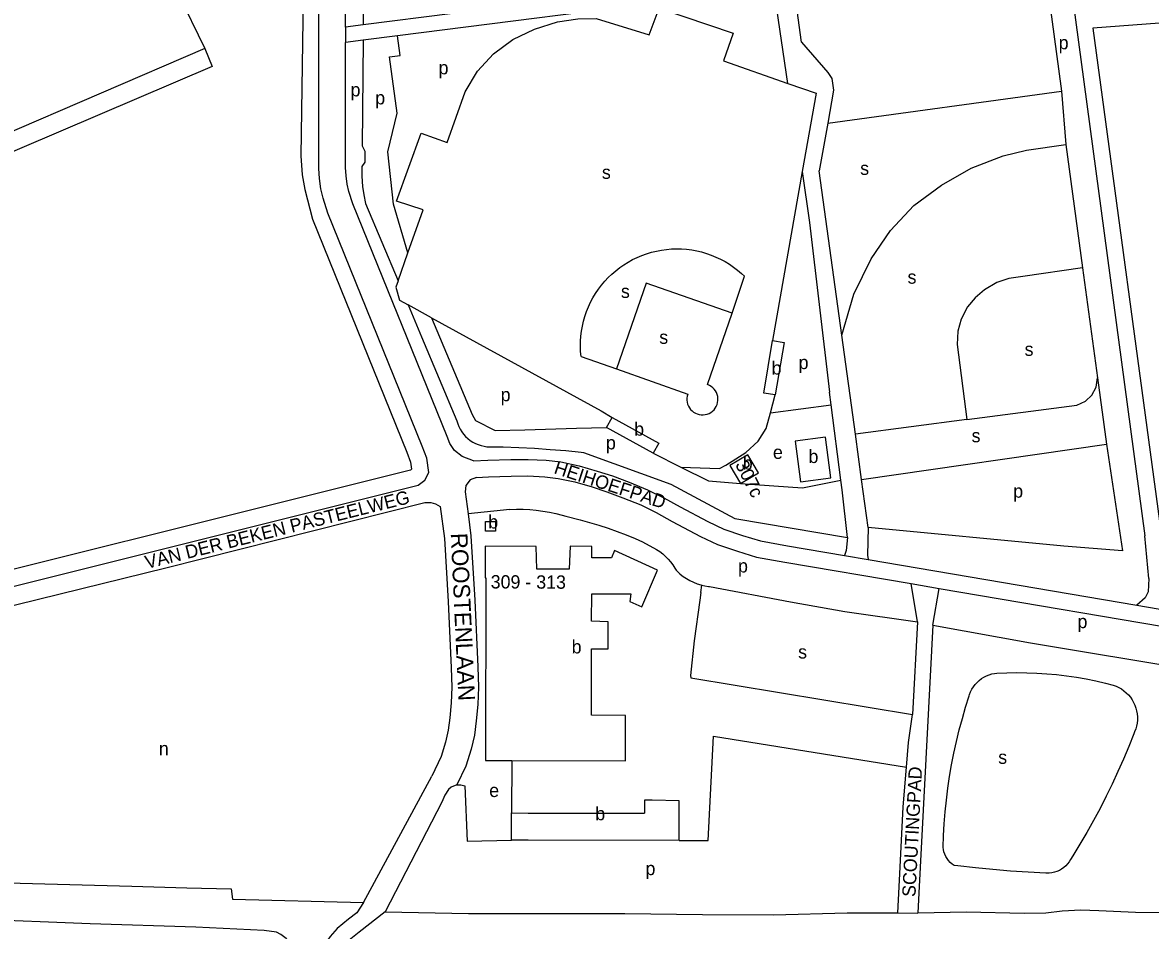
# Model space of a CAD drawing. Extents: x 161093 to 163177, y 379000 to 380904.
# Drawn here: x 162069 to 162407.9, y 379600.5 to 379873.5 of the extents above; entities that cross this region are included whole.
import ezdxf

# ---------------------------------------------------------------- set-up
doc = ezdxf.new("R2010")
doc.units = 0
for name, color, linetype in [('BLT_Basislijn', 7, 'Continuous'), ('BLT_Bebouwing', 7, 'Continuous'), ('BLT_Centroide', 7, 'Continuous'), ('BLT_Huisnummer', 7, 'Continuous'), ('BLT_Huisnummer_reeks', 7, 'Continuous'), ('BLT_Straatnaam', 7, 'Continuous'), ('BLT_Straatnaam_verkleind', 7, 'Continuous')]:
    doc.layers.add(name, color=color, linetype=linetype)

msp = doc.modelspace()

# ---------------------------------------------------------------- linework, layer by layer
at = {"layer": 'BLT_Basislijn'}
for p, q in [((162378.62, 379925.25), (162406.17, 379719.19)), ((162153.42, 379885.29), (162152.67, 379833.48)), ((162294.71, 379884.06), (162181.67, 379869.53)), ((162298.98, 379855.19), (162294.71, 379884.06)), ((162171.37, 379872.79), (162166.01, 379872.11)), ((162166.01, 379872.11), (162166.02, 379867.52)), ((162181.67, 379869.53), (162171.33, 379868.2)), ((162390.62, 379871.78), (162411.12, 379719.86)), ((162171.33, 379868.2), (162166.02, 379867.52)), ((162123.8, 379865.74), (162013.53, 379818.24)), ((162310.93, 379843.25), (162381.18, 379852.9)), ((162381.18, 379852.9), (162382.49, 379836.84)), ((162382.49, 379836.84), (162387.49, 379799.81)), ((162303.23, 379828.69), (162294.38, 379777.9)), ((162303.23, 379828.69), (162305.5, 379813.39)), ((162172.07, 379819.1), (162181.83, 379795.89)), ((162305.5, 379813.39), (162311.45, 379762.39)), ((162181.83, 379795.89), (162184.82, 379804.31)), ((162387.49, 379799.81), (162391.98, 379766.71)), ((162282.18, 379786.18), (162285.96, 379797.21)), ((162184.88, 379788.63), (162188.93, 379779)), ((162191.93, 379784.76), (162184.88, 379788.63)), ((162191.93, 379784.76), (162204.15, 379755.69)), ((162274.81, 379764.64), (162282.18, 379786.18)), ((162188.93, 379779), (162199.54, 379753.75)), ((162236.83, 379773.13), (162247.44, 379769.38)), ((162247.44, 379769.38), (162268.89, 379761.78)), ((162391.98, 379766.71), (162394.72, 379746.73)), ((162293.72, 379756.17), (162295.19, 379761.55)), ((162311.94, 379758.61), (162311.45, 379762.39)), ((162293.72, 379756.17), (162311.94, 379758.61)), ((162314.88, 379735.89), (162311.94, 379758.61)), ((162242.88, 379756.79), (162246.14, 379754.78)), ((162352.74, 379754.15), (162319.26, 379749.71)), ((162321.13, 379736.15), (162319.26, 379749.71)), ((162321.13, 379736.15), (162394.72, 379746.73)), ((162315.26, 379732.98), (162314.88, 379735.89)), ((162323.12, 379721.67), (162321.13, 379736.15)), ((162316.89, 379718.68), (162315.26, 379732.98)), ((162215.44, 379727.12), (162202.86, 379725.75)), ((162232.22, 379725.08), (162236.57, 379723.99)), ((162255.3, 379717.36), (162259.51, 379715.05)), ((162407.37, 379706.38), (162406.17, 379719.19)), ((162272.77, 379702.15), (162273.07, 379704.38)), ((162337.89, 379693.3), (162335.99, 379704.81)), ((162342.48, 379692.3), (162344.38, 379703.38)), ((162337.89, 379693.3), (162336.41, 379665.42)), ((162342.48, 379692.3), (162338.34, 379611.84)), ((162269.82, 379676.5), (162336.41, 379665.42)), ((162335.24, 379657.03), (162336.41, 379665.42)), ((162216.05, 379651.66), (162215.91, 379635.86)), ((162332.04, 379605.84), (162332.72, 379619.57)), ((162338.34, 379611.84), (162338.01, 379605.69)), ((162332.04, 379605.84), (162338.01, 379605.69))]:
    msp.add_line(p, q, dxfattribs=at)
for points in [[(162160.75, 379816.24), (162159.29, 379820.67), (162158.68, 379823.55), (162158.25, 379826.59), (162158.02, 379829.61), (162158.01, 379873.49), (162158.25, 379931.81), (162158.67, 380027.65), (162158.78, 380047.6)], [(162166.01, 379872.11), (162166.25, 379931.78), (162166.67, 380027.84)], [(162171.8, 380008.48), (162171.73, 380000), (162171.83, 379985.21), (162171.58, 379944.32), (162171.46, 379881.89), (162171.37, 379872.79)], [(162067.03, 379977.72), (162075.14, 379965.67), (162123.8, 379865.74)], [(162367.14, 379959.73), (162371.63, 379923.75), (162381.18, 379852.9)], [(162303.04, 379867.59), (162291.99, 379948.53)], [(162196.38, 379891.02), (162198.3, 379876.22), (162171.37, 379872.79)], [(162567.03, 379892.57), (162455.56, 379878.15), (162418.63, 379873.91), (162390.62, 379871.78)], [(162184.82, 379804.31), (162189.38, 379817.17), (162181.39, 379819.82), (162188.75, 379840.23), (162196.57, 379837.41), (162201.99, 379852.7), (162205.66, 379858.87), (162210.55, 379864.14), (162216.34, 379868.38), (162222.85, 379871.49), (162229.7, 379873.76), (162235.88, 379874.67), (162241.35, 379874.72), (162257.33, 379869.81), (162260.33, 379877.83), (162282.55, 379870.3), (162279.66, 379862.02), (162298.98, 379855.19)], [(162184.82, 379804.31), (162180.48, 379818.86), (162178.79, 379834.64), (162181.58, 379846.28), (162179.29, 379863.24), (162182.43, 379863.65), (162181.67, 379869.53)], [(162204.46, 379741.71), (162201.06, 379743.07), (162198.83, 379744.89), (162197.39, 379746.92), (162196.56, 379749.1), (162168.27, 379818.99), (162167.03, 379822.75), (162166.56, 379824.95), (162166.21, 379827.46), (162166.02, 379829.91), (162166.02, 379867.52)], [(162171.33, 379868.2), (162171.01, 379836.47), (162171.86, 379834.86), (162171.81, 379831.57), (162170.96, 379830.25), (162170.92, 379827.37), (162171.13, 379824.27), (162171.56, 379821.74), (162172.07, 379819.1)], [(162303.04, 379867.59), (162310.92, 379858.52), (162312.13, 379856.66), (162312.71, 379853.18), (162310.93, 379843.25)], [(162123.8, 379865.74), (162125.94, 379860.32), (161988.77, 379801.65)], [(162298.98, 379855.19), (162307.47, 379852.31), (162303.23, 379828.69)], [(162310.93, 379843.25), (162308.36, 379828.96)], [(162315.16, 379779.53), (162318.73, 379791.8), (162323.95, 379802.51), (162329.82, 379810.96), (162336.8, 379818.52), (162345.1, 379824.61), (162354, 379829.77), (162363.63, 379833.41), (162370.63, 379835.13), (162382.49, 379836.84)], [(162152.67, 379833.48), (162153.02, 379827.68), (162153.86, 379823.29), (162156.11, 379814.36)], [(162315.16, 379779.53), (162308.36, 379828.96)], [(162190.48, 379742.58), (162189.12, 379746.18), (162160.75, 379816.24)], [(162156.11, 379814.36), (162184.46, 379744.36), (162185.61, 379741.33)], [(162236.83, 379773.13), (162236.69, 379774.65), (162236.64, 379776.17), (162236.66, 379777.7), (162236.77, 379779.22), (162236.95, 379780.73), (162237.22, 379782.23), (162237.56, 379783.72), (162237.98, 379785.18), (162238.48, 379786.62), (162239.05, 379788.03), (162239.69, 379789.41), (162240.41, 379790.76), (162241.19, 379792.07), (162242.05, 379793.33), (162242.96, 379794.54), (162243.95, 379795.71), (162244.99, 379796.82), (162246.08, 379797.88), (162247.24, 379798.88), (162248.44, 379799.82), (162249.69, 379800.69), (162250.98, 379801.49), (162252.32, 379802.23), (162253.69, 379802.89), (162255.09, 379803.49), (162256.52, 379804), (162257.98, 379804.45), (162259.46, 379804.81), (162260.96, 379805.1), (162262.47, 379805.3), (162263.99, 379805.43), (162265.51, 379805.48), (162267.03, 379805.45), (162268.55, 379805.34), (162270.07, 379805.15), (162271.57, 379804.88), (162273.05, 379804.53), (162274.51, 379804.1), (162275.95, 379803.6), (162277.36, 379803.02), (162278.74, 379802.37), (162280.08, 379801.65), (162281.38, 379800.86), (162282.64, 379800), (162283.86, 379799.08), (162285.02, 379798.09), (162285.96, 379797.21)], [(162387.49, 379799.81), (162369.55, 379797.12), (162365.35, 379796.55), (162361.78, 379795.34), (162357.99, 379793.16), (162355.24, 379790.79), (162352.93, 379788), (162351.02, 379784.32), (162350.04, 379780.69), (162349.83, 379776.7), (162352.74, 379754.15)], [(162181.83, 379795.89), (162181.14, 379793.96), (162182.32, 379790.03), (162184.88, 379788.63)], [(162282.18, 379786.18), (162256.36, 379795.12), (162247.44, 379769.38)], [(162191.93, 379784.76), (162242.88, 379756.79)], [(162319.26, 379749.71), (162315.16, 379779.53)], [(162268.89, 379761.78), (162268.73, 379761.2), (162268.64, 379760.59), (162268.63, 379759.98), (162268.7, 379759.37), (162268.85, 379758.78), (162269.08, 379758.21), (162269.38, 379757.68), (162269.74, 379757.19), (162270.17, 379756.76), (162270.65, 379756.38), (162271.18, 379756.07), (162271.74, 379755.82), (162272.33, 379755.66), (162272.93, 379755.57), (162273.54, 379755.56), (162274.15, 379755.64), (162274.74, 379755.79), (162275.31, 379756.01), (162275.84, 379756.31), (162276.33, 379756.68), (162276.77, 379757.1), (162277.14, 379757.58), (162277.46, 379758.11), (162277.7, 379758.67), (162277.86, 379759.26), (162277.95, 379759.86), (162277.96, 379760.47), (162277.88, 379761.08), (162277.73, 379761.67), (162277.51, 379762.24), (162277.21, 379762.77), (162276.84, 379763.26), (162276.42, 379763.7), (162275.93, 379764.08), (162275.41, 379764.39), (162274.81, 379764.64)], [(162352.74, 379754.15), (162385.77, 379758.52), (162388.34, 379759.64), (162390.33, 379761.51), (162391.59, 379763.91), (162391.98, 379766.71)], [(162204.15, 379755.69), (162205.08, 379753.9), (162210.99, 379750.87), (162219.91, 379751.02), (162235.42, 379751.57), (162244.46, 379751.72)], [(162266.85, 379739.82), (162278.43, 379739.43), (162280.3, 379740.47), (162286.3, 379744.28), (162290.01, 379747.6), (162292.42, 379751.42), (162293.72, 379756.17)], [(162199.54, 379753.75), (162199.8, 379752.89), (162200.13, 379752.04), (162200.53, 379751.23), (162201.01, 379750.46), (162201.55, 379749.73), (162202.15, 379749.05), (162202.81, 379748.43), (162203.52, 379747.87), (162204.28, 379747.38), (162205.08, 379746.95), (162205.92, 379746.6), (162206.78, 379746.32), (162207.67, 379746.12), (162208.56, 379745.99), (162208.75, 379745.98)], [(162208.75, 379745.98), (162213.45, 379745.9), (162218.15, 379745.74), (162222.85, 379745.51), (162227.54, 379745.19), (162232.22, 379744.8), (162236.9, 379744.32), (162237.55, 379744.25)], [(162237.55, 379744.25), (162263.75, 379734.74), (162283.04, 379724.37), (162316.89, 379718.68)], [(162394.72, 379746.73), (162399.46, 379714.71), (162381.91, 379716.11), (162323.12, 379721.67)], [(162185.61, 379741.33), (162185.91, 379739.2), (162185.61, 379738.96), (162014.73, 379696.21)], [(162015.88, 379691.47), (162187.88, 379734.37), (162189.84, 379735.93), (162191.1, 379738.2), (162190.48, 379742.58)], [(162204.46, 379741.71), (162208.85, 379741.95), (162215.72, 379742.11), (162220.91, 379742.18), (162226.35, 379741.91), (162230.75, 379741.4), (162236.21, 379740.28), (162241.67, 379738.67), (162246.26, 379737.18), (162251.23, 379735.29), (162256.83, 379733.06), (162261.67, 379730.63), (162266.63, 379727.88), (162274.9, 379723.48), (162279.71, 379721.22), (162285.32, 379719.32), (162290.69, 379717.68), (162298.88, 379716.2), (162315.93, 379713.3)], [(162258.47, 379744.01), (162266.85, 379739.82)], [(162266.85, 379739.82), (162275.07, 379735.71), (162284.75, 379734.93)], [(162205.36, 379736.75), (162203.5, 379735.99), (162202.22, 379734.32), (162201.97, 379732.4), (162202.86, 379725.75)], [(162205.36, 379736.75), (162209.05, 379736.95), (162215.82, 379737.12), (162220.81, 379737.18), (162225.94, 379736.93), (162229.96, 379736.46), (162235, 379735.43), (162240.19, 379733.9), (162244.6, 379732.46), (162249.42, 379730.63), (162254.78, 379728.49), (162259.34, 379726.21), (162264.24, 379723.49), (162272.67, 379719.01), (162277.84, 379716.57), (162283.79, 379714.56), (162289.51, 379712.81), (162298.02, 379711.28), (162335.99, 379704.81)], [(162284.75, 379734.93), (162303.34, 379733.63), (162314.88, 379735.89)], [(162006.2, 379683.74), (162048.1, 379693.81), (162112.09, 379709.59), (162189.91, 379729.16), (162191.71, 379729.23), (162193.12, 379728.84), (162194.49, 379728.03)], [(162194.49, 379728.03), (162195.78, 379718.38), (162196.9, 379699.47), (162197.8, 379679.46), (162197.97, 379673.71), (162197.82, 379669.01), (162197.39, 379664.48), (162196.88, 379660.73), (162196.05, 379657.13), (162194.75, 379652.86), (162191.99, 379646.9)], [(162215.44, 379727.12), (162217.43, 379727.18), (162219.42, 379727.16), (162221.4, 379727.06), (162223.38, 379726.89), (162225.36, 379726.63), (162227.31, 379726.29), (162229.26, 379725.87), (162231.18, 379725.38), (162232.22, 379725.08)], [(162202.86, 379725.75), (162203.75, 379719.15), (162204.89, 379699.89), (162205.79, 379679.76), (162205.98, 379673.7), (162205.81, 379668.51), (162205.34, 379663.56), (162204.76, 379659.28), (162203.78, 379655.06), (162202.22, 379649.94), (162199.5, 379644.29)], [(162236.57, 379723.99), (162239.38, 379723.24), (162242.18, 379722.41), (162244.94, 379721.51), (162247.69, 379720.53), (162250.4, 379719.48), (162253.09, 379718.36), (162255.3, 379717.36)], [(162323.12, 379721.67), (162322.92, 379713.4), (162323.12, 379712.07)], [(162316.89, 379718.68), (162316.49, 379714.77), (162315.93, 379713.3)], [(162259.51, 379715.05), (162260.45, 379714.43), (162261.35, 379713.75), (162262.19, 379713.01), (162262.98, 379712.2), (162263.71, 379711.35), (162264.38, 379710.44), (162265, 379709.47)], [(162315.93, 379713.3), (162323.12, 379712.07)], [(162323.12, 379712.07), (162403.83, 379698.33)], [(162265, 379709.47), (162265.44, 379708.83), (162265.95, 379708.24), (162266.51, 379707.71), (162267.12, 379707.24), (162267.52, 379706.99)], [(162267.52, 379706.99), (162268.51, 379706.34), (162269.54, 379705.75), (162270.61, 379705.24), (162271.71, 379704.8), (162272.84, 379704.43), (162273.07, 379704.38)], [(162273.07, 379704.38), (162273.99, 379704.15), (162275.16, 379703.93), (162275.42, 379703.9)], [(162275.42, 379703.9), (162299.74, 379699.36), (162316.1, 379696.39), (162337.89, 379693.3)], [(162335.99, 379704.81), (162344.38, 379703.38)], [(162407.37, 379706.38), (162407.17, 379702.39), (162406.31, 379700.53), (162403.83, 379698.33)], [(162272.77, 379702.15), (162272.46, 379699.89), (162270.76, 379687.6), (162269.66, 379677.19), (162269.82, 379676.5)], [(162344.38, 379703.38), (162423.68, 379689.88), (162433.62, 379687.88), (162440.37, 379686.05), (162445.64, 379683.92), (162455.23, 379679.25), (162552.44, 379632.6), (162564.94, 379626.19), (162570.24, 379623.09), (162578.23, 379617.79), (162585.4, 379612.96), (162594.31, 379607), (162598.81, 379604.14), (162603.77, 379602.02)], [(162403.83, 379698.33), (162413.68, 379696.65)], [(162342.48, 379692.3), (162371.81, 379687.06), (162420.68, 379678.91), (162427.11, 379680.69), (162429.51, 379680.85), (162430.36, 379680.54)], [(162353.56, 379671.47), (162353.86, 379672.28), (162354.24, 379673.05), (162354.69, 379673.79), (162355.21, 379674.49), (162355.79, 379675.13), (162356.42, 379675.72), (162357.11, 379676.24), (162357.84, 379676.7), (162358.61, 379677.09), (162359.41, 379677.41), (162360.24, 379677.65), (162361.09, 379677.82), (162361.78, 379677.89)], [(162361.78, 379677.89), (162364.77, 379678.02), (162367.76, 379678.06), (162370.75, 379678.03), (162373.74, 379677.91), (162376.72, 379677.72), (162379.7, 379677.44), (162382.67, 379677.09), (162385.63, 379676.65), (162388.58, 379676.14), (162391.51, 379675.55), (162394.42, 379674.88), (162396.71, 379674.29)], [(162396.71, 379674.29), (162397.57, 379673.98), (162398.4, 379673.59), (162399.19, 379673.13), (162399.93, 379672.6), (162400.63, 379672.01), (162401.27, 379671.36), (162401.86, 379670.65), (162402.38, 379669.9), (162402.83, 379669.11), (162403.21, 379668.27), (162403.52, 379667.41), (162403.75, 379666.53), (162403.9, 379665.63), (162403.98, 379664.72), (162403.97, 379663.8), (162403.88, 379662.89), (162403.72, 379661.99), (162403.47, 379661.11), (162403.15, 379660.25), (162402.88, 379659.65)], [(162345.6, 379625.47), (162345.73, 379629.04), (162345.93, 379632.61), (162346.22, 379636.17), (162346.59, 379639.73), (162347.04, 379643.28), (162347.56, 379646.81), (162348.17, 379650.34), (162348.85, 379653.85), (162349.62, 379657.34), (162350.46, 379660.81), (162351.38, 379664.27), (162352.37, 379667.7), (162353.44, 379671.11), (162353.56, 379671.47)], [(162402.88, 379659.65), (162401.37, 379655.83), (162399.79, 379652.04), (162398.14, 379648.28), (162396.41, 379644.55), (162394.61, 379640.86), (162392.74, 379637.21), (162390.8, 379633.59), (162388.79, 379630.01), (162386.71, 379626.47), (162384.57, 379622.97), (162383.87, 379621.87)], [(162266.29, 379627.56), (162275.01, 379627.54), (162276.57, 379658.93), (162334.6, 379649.66)], [(162334.6, 379649.66), (162335.24, 379657.03)], [(162332.72, 379619.57), (162333.57, 379637.71), (162334.6, 379649.66)], [(162171.47, 379608.91), (162191.99, 379646.9)], [(162199.5, 379644.29), (162197.81, 379643.59), (162197.01, 379642.95), (162195.93, 379641.16), (162195, 379639.15), (162177.94, 379606.17)], [(162199.5, 379644.29), (162200.72, 379644.3), (162201.89, 379644.02)], [(162201.89, 379644.02), (162202.64, 379627.33), (162215.89, 379627.7)], [(162348.94, 379620.07), (162348.32, 379620.5), (162347.75, 379620.99), (162347.23, 379621.54), (162346.78, 379622.14), (162346.39, 379622.79), (162346.08, 379623.47), (162345.83, 379624.18), (162345.67, 379624.92), (162345.6, 379625.47)], [(162154.44, 379587.46), (162154.31, 379590.38), (162153.73, 379592.07), (162152.3, 379593.86), (162150.56, 379595.82), (162148.24, 379598.09), (162146.65, 379599.3), (162145.28, 379599.99), (162141.64, 379600.52), (162121.07, 379601.52), (162089.29, 379602.54), (162054.12, 379603.88), (162011.17, 379606.32), (161966.06, 379609.87), (161932.99, 379612.83), (161886.58, 379616.22), (161843.25, 379618.32), (161808.99, 379620.26), (161784.42, 379621.55), (161777.14, 379621.71)], [(162376.42, 379617.76), (162371.14, 379618.03), (162365.86, 379618.39), (162360.59, 379618.82), (162355.32, 379619.34), (162350.07, 379619.93), (162348.94, 379620.07)], [(162383.87, 379621.87), (162383.46, 379621.19), (162382.99, 379620.56), (162382.45, 379619.98), (162381.86, 379619.45), (162381.22, 379618.99), (162380.54, 379618.6), (162379.81, 379618.27), (162379.06, 379618.02), (162378.29, 379617.85), (162377.51, 379617.76), (162376.72, 379617.74), (162376.42, 379617.76)], [(162018.02, 379617.13), (162053.26, 379615.11), (162101.88, 379613.84), (162118.38, 379613.34), (162131.74, 379613.09), (162132.12, 379609.94), (162171.47, 379608.91)], [(162171.47, 379608.91), (162169.44, 379605.85), (162167, 379603.94), (162163.54, 379601.08), (162161.44, 379598.67), (162160.03, 379596.68), (162158.86, 379594.34), (162157.72, 379590.92), (162157.34, 379587.94), (162157.32, 379587.36)], [(162177.94, 379606.17), (162170.14, 379600.04), (162167.13, 379597.56), (162165.3, 379595.26), (162163.94, 379592.87), (162163, 379590.41), (162162.55, 379588.37), (162162.5, 379587.17)], [(162177.94, 379606.17), (162202.96, 379605.59), (162226.14, 379605.59), (162249.96, 379605.59), (162273.27, 379605.34)], [(162273.27, 379605.34), (162294.62, 379605.21), (162316.8, 379605.84), (162332.04, 379605.84)], [(162577.85, 379607.42), (162576.65, 379605.31), (162529.77, 379605.46), (162514.02, 379605.84), (162495.37, 379605.65), (162483.71, 379605.72), (162468.66, 379605.53), (162452.4, 379605.91), (162438.35, 379606.16), (162427.65, 379606.03), (162414.92, 379605.84), (162403.39, 379605.91), (162392.37, 379606.47), (162386.95, 379606.66), (162381.34, 379606.35), (162376.49, 379605.72), (162370, 379605.59), (162352.61, 379606.03), (162338.01, 379605.69)]]:
    msp.add_lwpolyline(points, dxfattribs=at)
at = {"layer": 'BLT_Bebouwing'}
for p, q in [((162244.46, 379751.72), (162246.14, 379754.78)), ((162258.47, 379744.01), (162244.46, 379751.72)), ((162215.89, 379627.7), (162215.91, 379635.86))]:
    msp.add_line(p, q, dxfattribs=at)
for points in [[(162295.19, 379761.55), (162291.74, 379762.13), (162294.38, 379777.9)], [(162294.38, 379777.9), (162297.83, 379777.32), (162295.19, 379761.55)], [(162246.14, 379754.78), (162260.16, 379747.07), (162258.47, 379744.01)], [(162284.75, 379734.93), (162290.14, 379738.15), (162286.93, 379743.52), (162281.54, 379740.3), (162284.75, 379734.93)], [(162208.06, 379716.09), (162208.05, 379706.6), (162208.22, 379706.6), (162208.07, 379651.68)], [(162255.06, 379697.84), (162259.82, 379708.84), (162246.86, 379714.75), (162245.93, 379712.6), (162240.05, 379712.61), (162240.1, 379715.93), (162233.54, 379716.04), (162233.26, 379709.15), (162223.53, 379709.19), (162223.33, 379716.02), (162208.06, 379716.09)], [(162216.05, 379651.66), (162250.14, 379651.57), (162250.18, 379665.21), (162239.91, 379665.24), (162239.97, 379685.18), (162244.95, 379685.17), (162244.97, 379693.37), (162239.99, 379693.48), (162240.01, 379701.74), (162251.74, 379701.71), (162251.52, 379699.47), (162255.06, 379697.84)], [(162208.07, 379651.68), (162216.05, 379651.66)], [(162258.14, 379639.71), (162255.89, 379639.75), (162255.88, 379635.75)], [(162266.29, 379627.56), (162266.32, 379639.54), (162258.14, 379639.71)], [(162215.91, 379635.86), (162220.91, 379635.84), (162255.88, 379635.75)], [(162266.29, 379627.56), (162220.89, 379627.68), (162215.89, 379627.7)]]:
    msp.add_lwpolyline(points, dxfattribs=at)
for points in [[(162301.13, 379747.63), (162302.72, 379735.43), (162311.85, 379736.62), (162310.26, 379748.82)], [(162208.15, 379723.53), (162211.11, 379723.52), (162211.11, 379720.57), (162208.14, 379720.58)]]:
    msp.add_lwpolyline(points, close=True, dxfattribs=at)

# ---------------------------------------------------------------- texts
at = {"layer": 'BLT_Centroide'}
for s, p in [('p', (162380.33, 379865.47)), ('p', (162194.01, 379857.94)), ('p', (162167.57, 379851.32)), ('p', (162174.98, 379848.91)), ('s', (162243.09, 379826.51)), ('s', (162320.69, 379827.7)), ('s', (162334.92, 379794.99)), ('s', (162248.8, 379790.71)), ('s', (162260.32, 379776.91)), ('s', (162370.09, 379773.29)), ('b', (162294.08, 379767.66)), ('p', (162302.19, 379769.32)), ('p', (162212.67, 379759.65)), ('b', (162252.78, 379749.3)), ('p', (162244.3, 379745.18)), ('s', (162354.16, 379747.31)), ('e', (162294.48, 379742.32)), ('b', (162305.15, 379741.07)), ('b', (162285.41, 379739.09)), ('p', (162366.66, 379730.65)), ('b', (162208.95, 379721.39)), ('p', (162283.99, 379708.16)), ('p', (162385.98, 379691.43)), ('b', (162234, 379683.83)), ('s', (162302.05, 379682.29)), ('n', (162109.98, 379653.22)), ('s', (162362.16, 379650.62)), ('e', (162209.23, 379640.65)), ('b', (162241.1, 379633.66)), ('p', (162256.18, 379617.17))]:
    msp.add_text(s, height=4, dxfattribs=at).set_placement(p)
at = {"layer": 'BLT_Huisnummer'}
msp.add_text('307c', height=4, rotation=296.7366, dxfattribs=at).set_placement((162283.04, 379740.66))
at = {"layer": 'BLT_Huisnummer_reeks'}
msp.add_text('309 - 313', height=4, rotation=359.726, dxfattribs=at).set_placement((162209.67, 379703.37))
at = {"layer": 'BLT_Straatnaam'}
msp.add_text('ROOSTENLAAN', height=5, rotation=272.6482, dxfattribs=at).set_placement((162197.66, 379719.93))
at = {"layer": 'BLT_Straatnaam_verkleind'}
for s, height, rotation, p in [('HEIHOEFPAD', 4, 341.9395, (162228.42, 379738.04)), ('VAN DER BEKEN PASTEELWEG', 3.9999, 14.0595, (162106.37, 379709.2)), ('SCOUTINGPAD', 4, 87.053, (162337.28, 379610.54))]:
    msp.add_text(s, height=height, rotation=rotation, dxfattribs=at).set_placement(p)

doc.saveas('drawing.dxf')
